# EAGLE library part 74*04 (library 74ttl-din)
Hex INVERTER
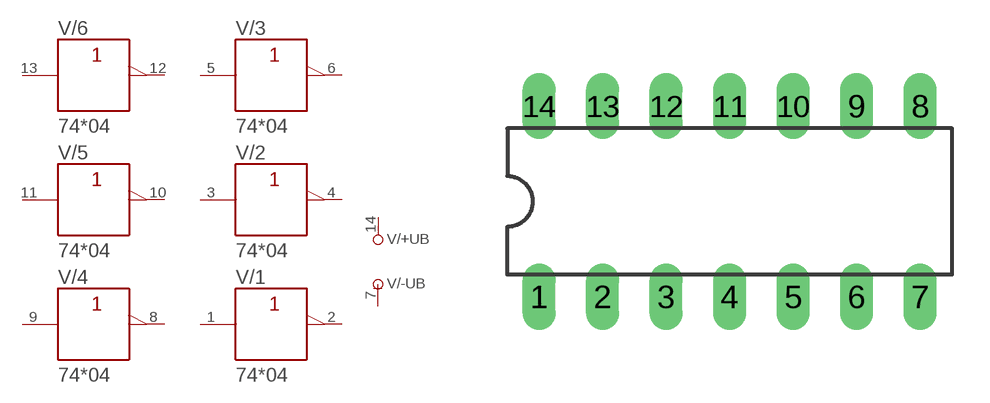
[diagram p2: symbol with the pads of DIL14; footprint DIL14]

Designator prefix V; gates /+UB=+UB /-UB=-UB /1=04 /2=04 /3=04 /4=04 /5=04 /6=04

## 7404N  [DIL14]
1  /1:A  in
2  /1:Y  out
3  /2:A  in
4  /2:Y  out
5  /3:A  in
6  /3:Y  out
7  /-UB:-UB  pwr
8  /4:Y  out
9  /4:A  in
10  /5:Y  out
11  /5:A  in
12  /6:Y  out
13  /6:A  in
14  /+UB:+UB  pwr

## Footprint DIL14 (pad centres in mm)
Dual In Line Package
drill 0.813 long: 1 -7.62,-3.81; 2 -5.08,-3.81; 3 -2.54,-3.81; 4 0,-3.81; 5 2.54,-3.81; 6 5.08,-3.81; 7 7.62,-3.81; 8 7.62,3.81; 9 5.08,3.81; 10 2.54,3.81; 11 0,3.81; 12 -2.54,3.81; 13 -5.08,3.81; 14 -7.62,3.81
